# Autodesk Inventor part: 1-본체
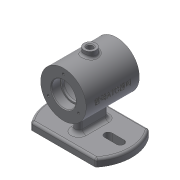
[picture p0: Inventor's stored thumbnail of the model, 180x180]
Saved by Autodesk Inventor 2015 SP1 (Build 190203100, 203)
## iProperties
Created: 2017-12
Part Number: 1-본체
Material: 일반
Document SubType Name: Modeling
Designer: C04
Density: 1 g/cm^3
Appearance: 기본값
Author: C04
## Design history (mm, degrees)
sketch "스케치1"
  geometry: L1 (-35, -42.426)-(-35, 42.426); L2 (35, -42.426)-(35, 42.426); L3 (35, 0)-(-35, 0); L4 (0, -24)-(0, -40); L5 (-5, -24)-(-5, -40); L6 (5, -40)-(5, -24); L7 (0, 24)-(0, 40); L8 (5, 24)-(5, 40); L9 (-5, 40)-(-5, 24); A1 r 55 centre (0, 0) between (-35, -42.426) and (35, -42.426); A2 r 55 centre (0, 0) between (35, 42.426) and (-35, 42.426); A3 r 5 centre (0, -24) between (5, -24) and (-5, -24); A4 r 5 centre (0, -40) between (-5, -40) and (5, -40); A5 r 5 centre (0, 24) between (-5, 24) and (5, 24); A6 r 5 centre (0, 40) between (5, 40) and (-5, 40); 4 further points
  constraints: 22 end point, 12 point on circle, 8 tangent, 6 centre point, 5 midpoint, 3 parallel, 3 vertical, 2 coincident
  dimensions: "d1" = 70 distance between parallel lines of L1 L2; "d2" = 5 radius of A6; "d3" = 5 radius of A4; "d4" = 24 vertical distance of L3.end L4.start; "d5" = 16 distance of L4.end L4.start; "d6" = 24 vertical distance of L7.start L3.start; "d7" = 16 distance of L7.end L7.start; "d8" = 55 radius of A1; "d9" = 55 radius of A2
extrude "돌출1" new body sketch "스케치1" distance "d10" = 10; taper "d11" = 0 deg
sketch "스케치3"
  geometry: L1 (0, 42.426)-(0, -42.426) reference; C1 r 30 at (62, 0); 1 further point
  constraints: 1 centre point
  dimensions: "d12" = 62 distance from line of L1 C1.centre; "d13" = 60 diameter of C1
extrude "돌출2" join sketch "스케치3" stored distance "d14" = 70; taper "d15" = 0 deg
sketch "스케치4"
  geometry: L1 (-15, 0)-(15, 0); L2 (-15, -5)-(15, -5); L3 (15, 5)-(-15, 5); A1 r 5 centre (-15, 0) between (-15, 5) and (-15, -5); A2 r 5 centre (15, 0) between (15, -5) and (15, 5); 3 further points
  constraints: 8 end point, 4 point on circle, 4 tangent, 2 centre point, 2 midpoint, 1 horizontal, 1 parallel, 1 vertical alignment
  dimensions: "d16" = 5 radius of A2; "d17" = 30 distance of L3.start L3.end
extrude "돌출3" join sketch "스케치4" stored distance "d18" = 70; taper "d19" = 0 deg; dims "d1" = 70, "d2" = 5, "d3" = 5, "d4" = 24, "d5" = 16, "d6" = 24, "d7" = 16, "d8" = 55, "d9" = 55
node "작업 평면1"
sketch "스케치5"
  geometry: C1 r 8 at (0, 0); 1 further point
  constraints: 1 centre point, 1 coincident
  dimensions: "d21" = 16 diameter of C1
extrude "돌출4" join sketch "스케치5" stored distance "d22" = 70; taper "d23" = 0 deg; dims "d1" = 70, "d2" = 5, "d3" = 5, "d4" = 24, "d5" = 16, "d6" = 24, "d7" = 16, "d8" = 55, "d9" = 55
sketch "스케치6"
  geometry: L1 (35, 32)-(35, 92) reference; L2 (35, 62)-(-35, 62); L3 (35, 62)-(23, 62); L4 (23, 62)-(23, 78); L5 (23, 78)-(35, 78); L6 (35, 78)-(35, 62); L7 (23, 62)-(20, 62); L8 (20, 62)-(20, 76); L9 (20, 76)-(23, 76); L10 (23, 76)-(23, 62); L11 (20, 62)-(-20, 62); L12 (-20, 62)-(-20, 87); L13 (-20, 87)-(20, 87); L14 (20, 87)-(20, 62); L15 (-20, 62)-(-23, 62); L16 (-23, 62)-(-23, 76); L17 (-23, 76)-(-20, 76); L18 (-20, 76)-(-20, 62); L19 (-23, 62)-(-35, 62); L20 (-35, 92)-(-35, 32) reference; L21 (-23, 62)-(-35, 62); L22 (-35, 62)-(-35, 78); L23 (-35, 78)-(-23, 78); L24 (-23, 78)-(-23, 62); 1 further point
  constraints: 44 end point, 10 parallel, 7 horizontal, 5 perpendicular, 1 midpoint, 1 point on line
  dimensions: "d24" = 32 diameter of L5 L2; "d26" = 70 distance of L2.start L2.end; "d27" = 28 diameter of L9 L2; "d28" = 28 diameter of L17 L2; "d29" = 12 distance of L4.end L5.end; "d31" = 40 distance of L12.end L13.end; "d32" = 50 diameter of L13 L11; "d33" = 3 distance of L8.end L9.end; "d34" = 12 distance of L22.end L23.end; "d35" = 32 diameter of L23 L2
revolve "회전1" sketch "스케치6" stored, may be unused: angle "d36" = 90 deg
sketch "스케치7"
  geometry: 1 further point
hole "구멍1" sketch "스케치7" at (0, 0) diameter "d37" = 8; stored, may be unused: countersink angle "d41" = 90 deg, drill point angle "d43" = 0 deg; dims "d38" = 6, "d39" = 4, "d40" = 2, "d42" = 8
fillet "모깎기1" dims "d44" = 5
fillet "모깎기2" dims "d45" = 3
fillet "모깎기3" dims "d46" = 3
fillet "모깎기4" dims "d47" = 5
chamfer "모따기1" distance "d48" = 1; stored, may be unused: second distance "d49" = 2, angle "d50" = 45 deg
fillet "모깎기5" dims "d51" = 3
fillet "모깎기6" dims "d52" = 0.3
node "작업 평면3"
sketch "스케치9"
  geometry: L1 (-35, 92)-(-35, 32) reference; L2 (-35, 62)-(35, 62); L3 (35, 45)-(35, 79) reference; 2 further points
  constraints: 2 end point, 2 midpoint, 1 other
  dimensions: "d56" = 30 vertical distance of L1.start point (0, 62); "d57" = 35 horizontal distance of L1.start point (0, 62)
feature "엠보싱1" sketch "스케치9" dims "d58" = 0.5, "d59" = 0
sketch "스케치10" dims "d60" = 46
  geometry: 3 further points
  constraints: 1 vertical alignment, 2 other
hole "구멍2" sketch "스케치10" at (0, 23) diameter "d61" = 3.242; stored, may be unused: countersink angle "d65" = 90 deg, drill point angle "d67" = 118 deg; dims "d62" = 8, "d63" = 4, "d64" = 2, "d66" = 10
fillet "모깎기7" dims "d71" = 3
node "솔리드1"
pattern_circular "원형 패턴1" dims angle "d69" = 360 deg
mirror "대칭1"
other parameters: "d20" = 99
